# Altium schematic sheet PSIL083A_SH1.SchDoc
size 431 x 279 mm; Date: Not shown in title block; ApprovedBy: Not shown in title block; CheckedBy: Not shown in title block; Author: Not shown in title block; CompanyName: Not shown in title block; Engineer: Not shown in title block; Organization: Not shown in title block; Address1: Not shown in title block; Address2: Not shown in title block; Address3: Not shown in title block; Address4: Not shown in title block; DocumentNumber: 1; Revision: Use project parameter SCH_Rev; SheetNumber: 1; SheetTotal: 3; PageSetup: Record=PageOptions¦CenterHorizontal=True¦CenterVertical=True¦PrintScale=1.00¦XCorrection=1.00¦YCorrection=1.00¦PrintKind=0¦BorderSize=5000000¦LeftOffset=0¦BottomOffset=0¦Orientation=2¦PaperLength=1000¦PaperWidth=1000¦Scale=100¦PaperSource=15¦PrintQuality=600¦MediaType=1¦DitherType=10¦PaperKind=Letter¦PrintScaleMode=1
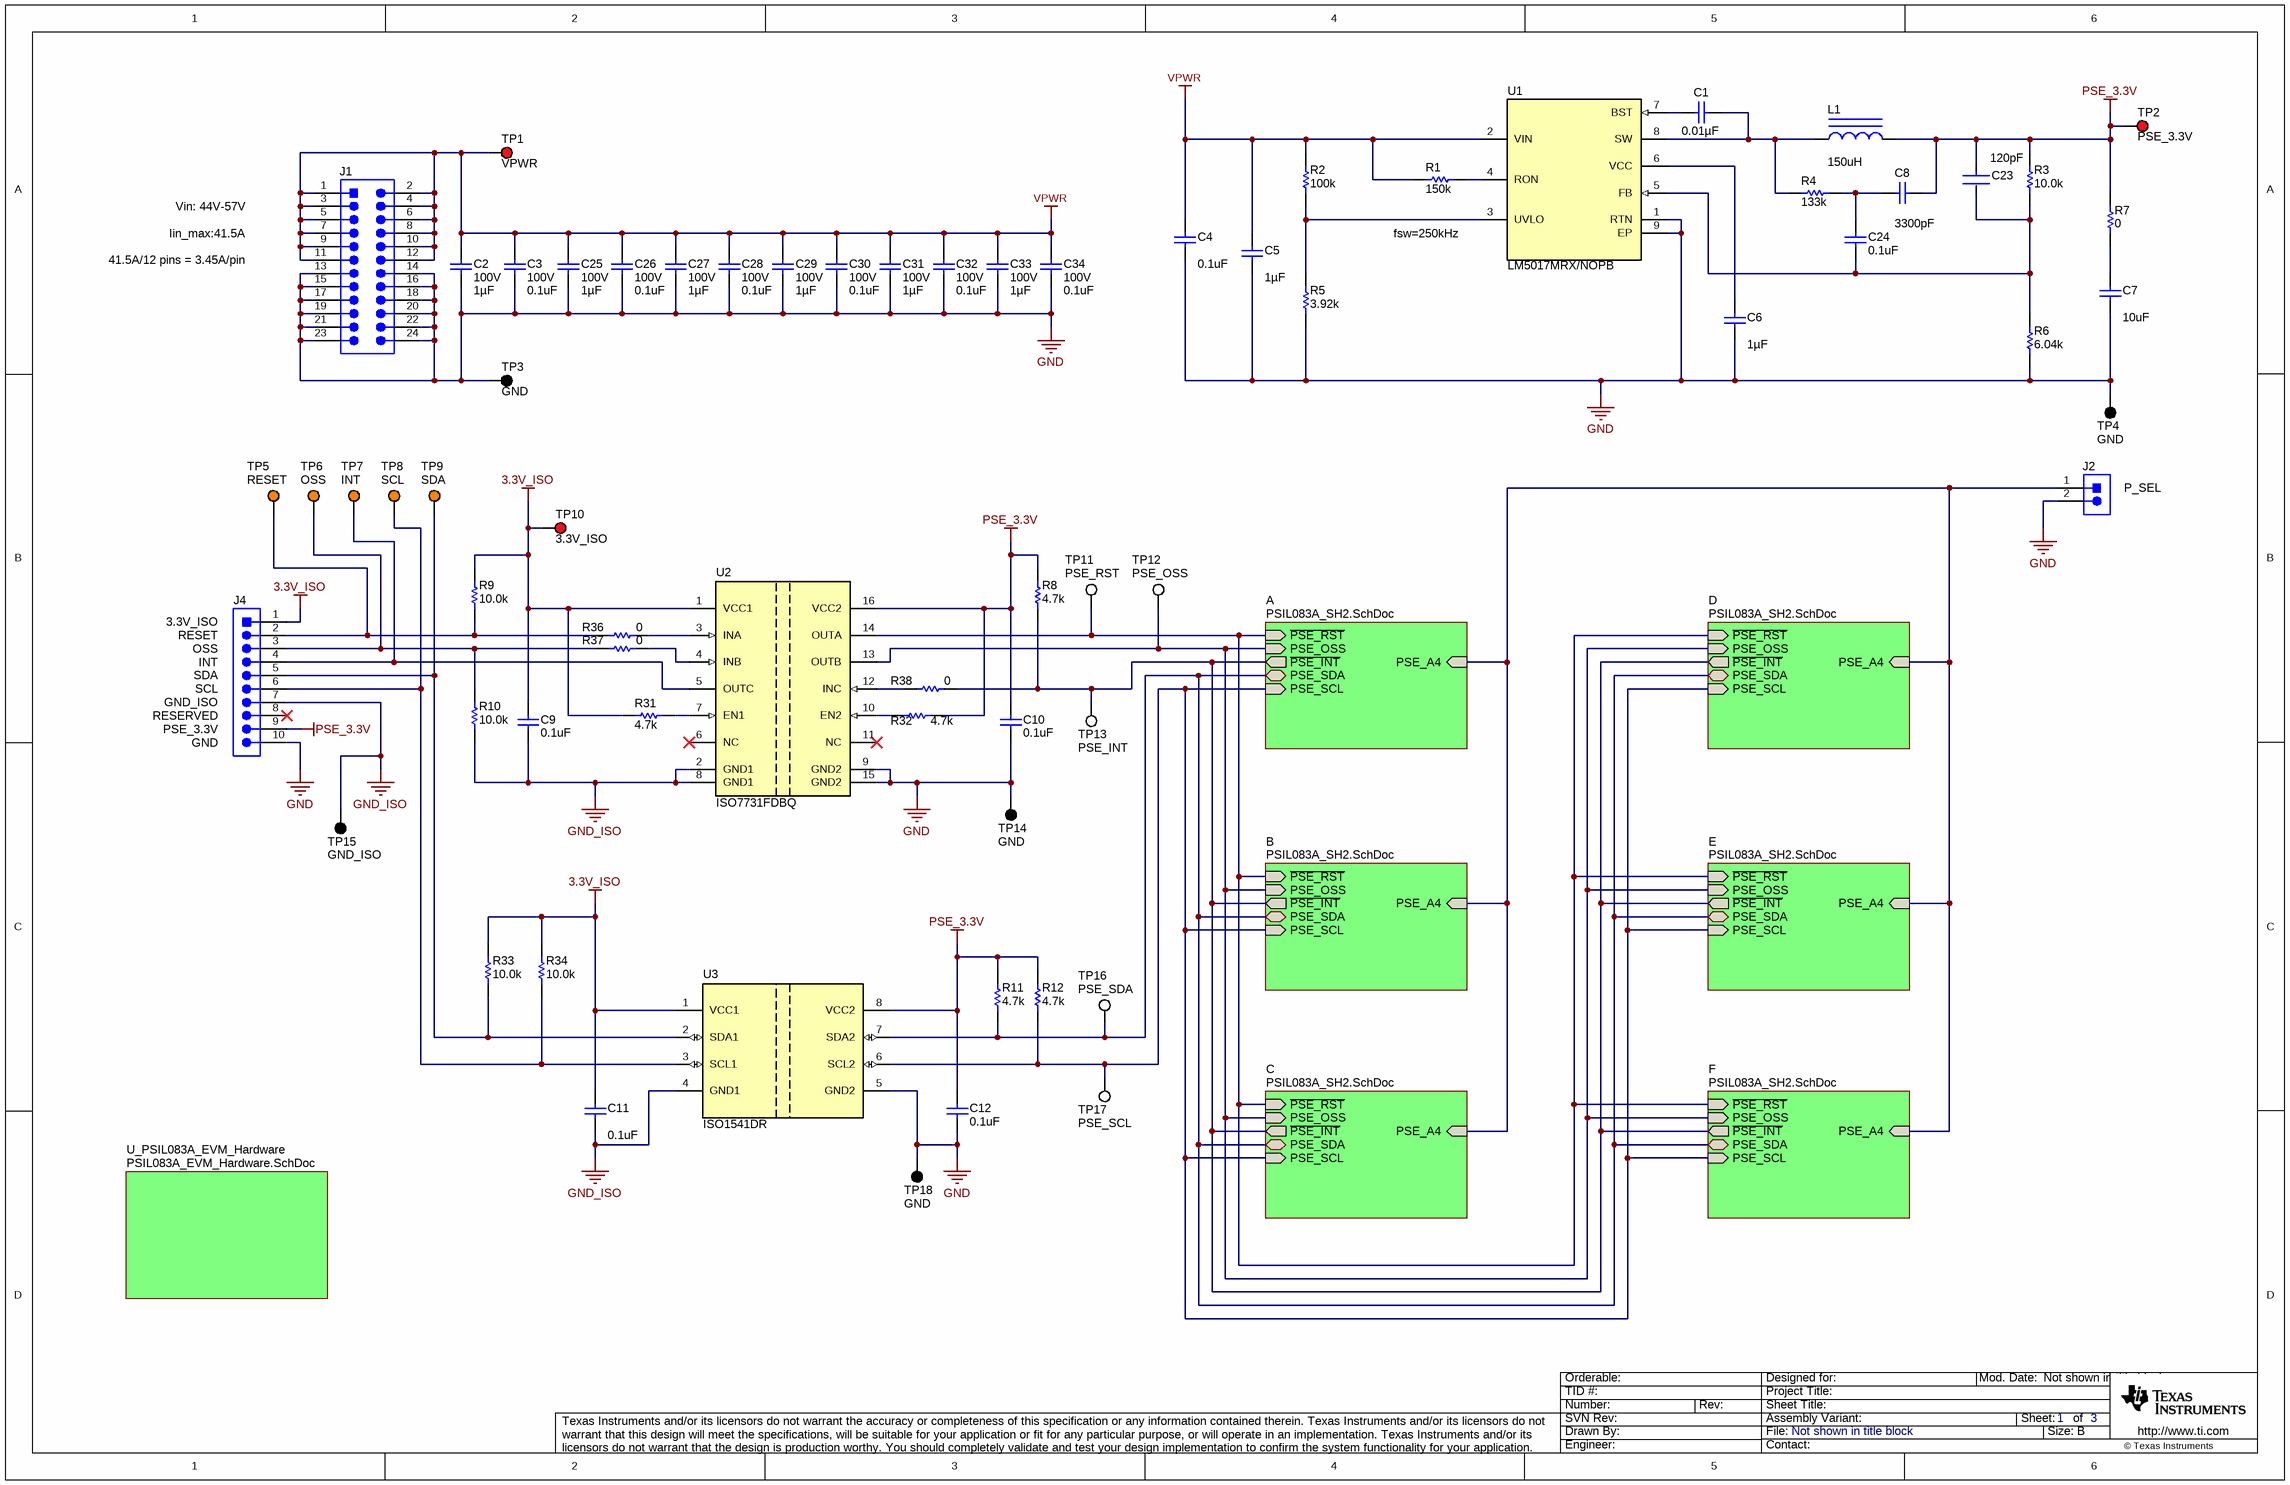
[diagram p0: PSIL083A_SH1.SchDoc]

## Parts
C1  ValueDisplayed: 0.01µF  [0603]  (hidden comment: 885012206089)
C2  VDC_V: 100V  ValueDisplayed: 1µF  [1206]  (hidden comment: GCJ31CR72A105KA01K)
C3  VDC_V: 100V  ValueDisplayed: 0.1uF  [0805_HV]  (hidden comment: C2012X7R2A104K125AA)
C4  ValueDisplayed: 0.1uF  [0805_HV]  (hidden comment: C2012X7R2A104K125AA)
C5  ValueDisplayed: 1µF  [1206]  (hidden comment: GCJ31CR72A105KA01K)
C6  ValueDisplayed: 1µF  [0603]  (hidden comment: CL10B105MO8NNWC)
C7  ValueDisplayed: 10uF  [0805_HV]  (hidden comment: 885012207026)
C8  ValueDisplayed: 3300pF  [0603]  (hidden comment: GRM1885C1H332JA01D)
C9  ValueDisplayed: 0.1uF  [0603]  (hidden comment: 885012206095)
C10  ValueDisplayed: 0.1uF  [0603]  (hidden comment: 885012206095)
C11  ValueDisplayed: 0.1uF  [0603]  (hidden comment: 885012206095)
C12  ValueDisplayed: 0.1uF  [0603]  (hidden comment: 885012206095)
C23  Cap_F: 120pF  [FP-GCM1555C1H121FA16D_0402-MFG]  (hidden comment: GCM1555C1H121FA16D)
C24  ValueDisplayed: 0.1uF  [0603]  (hidden comment: 885012206095)
C25  VDC_V: 100V  ValueDisplayed: 1µF  [1206]  (hidden comment: GCJ31CR72A105KA01K)
C26  VDC_V: 100V  ValueDisplayed: 0.1uF  [0805_HV]  (hidden comment: C2012X7R2A104K125AA)
C27  VDC_V: 100V  ValueDisplayed: 1µF  [1206]  (hidden comment: GCJ31CR72A105KA01K)
C28  VDC_V: 100V  ValueDisplayed: 0.1uF  [0805_HV]  (hidden comment: C2012X7R2A104K125AA)
C29  VDC_V: 100V  ValueDisplayed: 1µF  [1206]  (hidden comment: GCJ31CR72A105KA01K)
C30  VDC_V: 100V  ValueDisplayed: 0.1uF  [0805_HV]  (hidden comment: C2012X7R2A104K125AA)
C31  VDC_V: 100V  ValueDisplayed: 1µF  [1206]  (hidden comment: GCJ31CR72A105KA01K)
C32  VDC_V: 100V  ValueDisplayed: 0.1uF  [0805_HV]  (hidden comment: C2012X7R2A104K125AA)
C33  VDC_V: 100V  ValueDisplayed: 1µF  [1206]  (hidden comment: GCJ31CR72A105KA01K)
C34  VDC_V: 100V  ValueDisplayed: 0.1uF  [0805_HV]  (hidden comment: C2012X7R2A104K125AA)
J1  TSW-112-07-G-D  [TSW-112-07-G-D]  (value not drawn)
J2  TSW-102-07-G-S  [TSW-102-07-G-S]  (value not drawn)
J4  TSW-110-07-G-S  [TSW-110-07-G-S]  (value not drawn)
L1  ValueDisplayed: 150uH  [WE-TPC_6823]  (hidden comment: 744062151)
R1  ValueDisplayed: 150k  [0402]  (hidden comment: CRCW0402150KFKED)
R2  ValueDisplayed: 100k  [0402]  (hidden comment: CRCW0402100KFKED)
R3  ValueDisplayed: 10.0k  [0402]  (hidden comment: CRCW040210K0FKED)
R4  ValueDisplayed: 133k  [0402]  (hidden comment: CRCW0402133KFKED)
R5  ValueDisplayed: 3.92k  [0402]  (hidden comment: CRCW04023K92FKED)
R6  ValueDisplayed: 6.04k  [0402]  (hidden comment: CRCW04026K04FKED)
R7  ValueDisplayed: 0  [0603]  (hidden comment: RC0603JR-070RL)
R8  ValueDisplayed: 4.7k  [0402]  (hidden comment: CRCW04024K70JNED)
R9  ValueDisplayed: 10.0k  [0402]  (hidden comment: CRCW040210K0FKED)
R10  ValueDisplayed: 10.0k  [0402]  (hidden comment: CRCW040210K0FKED)
R11  ValueDisplayed: 4.7k  [0402]  (hidden comment: CRCW04024K70JNED)
R12  ValueDisplayed: 4.7k  [0402]  (hidden comment: CRCW04024K70JNED)
R31  ValueDisplayed: 4.7k  [0402]  (hidden comment: CRCW04024K70JNED)
R32  ValueDisplayed: 4.7k  [0402]  (hidden comment: CRCW04024K70JNED)
R33  ValueDisplayed: 10.0k  [0402]  (hidden comment: CRCW040210K0FKED)
R34  ValueDisplayed: 10.0k  [0402]  (hidden comment: CRCW040210K0FKED)
R36  ValueDisplayed: 0  [0402]  (hidden comment: ERJ-2GE0R00X)
R37  ValueDisplayed: 0  [0402]  (hidden comment: ERJ-2GE0R00X)
R38  ValueDisplayed: 0  [0402]  (hidden comment: ERJ-2GE0R00X)
TP1  VPWR  [Keystone5000]
TP2  PSE_3.3V  [Keystone5000]
TP3  GND  [Keystone5001]
TP4  GND  [Keystone5001]
TP5  RESET  [Keystone5003]
TP6  OSS  [Keystone5003]
TP7  INT  [Keystone5003]
TP8  SCL  [Keystone5003]
TP9  SDA  [Keystone5003]
TP10  3.3V_ISO  [Keystone5000]
TP11  PSE_RST  [Keystone5002]
TP12  PSE_OSS  [Keystone5002]
TP13  PSE_INT  [Keystone5002]
TP14  GND  [Keystone5001]
TP15  GND_ISO  [Keystone5001]
TP16  PSE_SDA  [Keystone5002]
TP17  PSE_SCL  [Keystone5002]
TP18  GND  [Keystone5001]
U1  LM5017MRX/NOPB  [DDA0008B_N]
U2  ISO7731FDBQ  [DBQ0016A_N]
U3  ISO1541DR  [D0008B_L]

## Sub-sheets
A = PSIL083A_SH2.SchDoc: ~{PSE_RST} (in), PSE_SCL (in), PSE_OSS (in), ~{PSE_INT} (out), PSE_A4 (in), PSE_SDA (bidir)
B = PSIL083A_SH2.SchDoc: ~{PSE_RST} (in), PSE_SCL (in), PSE_OSS (in), ~{PSE_INT} (out), PSE_A4 (in), PSE_SDA (bidir)
C = PSIL083A_SH2.SchDoc: ~{PSE_RST} (in), PSE_SCL (in), PSE_OSS (in), ~{PSE_INT} (out), PSE_A4 (in), PSE_SDA (bidir)
D = PSIL083A_SH2.SchDoc: ~{PSE_RST} (in), PSE_SCL (in), PSE_OSS (in), ~{PSE_INT} (out), PSE_A4 (in), PSE_SDA (bidir)
E = PSIL083A_SH2.SchDoc: ~{PSE_RST} (in), PSE_SCL (in), PSE_OSS (in), ~{PSE_INT} (out), PSE_A4 (in), PSE_SDA (bidir)
F = PSIL083A_SH2.SchDoc: ~{PSE_RST} (in), PSE_SCL (in), PSE_OSS (in), ~{PSE_INT} (out), PSE_A4 (in), PSE_SDA (bidir)
U_PSIL083A_EVM_Hardware = PSIL083A_EVM_Hardware.SchDoc: no entries

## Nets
3.3V_ISO: C9.1 C11.1 J4.1 R9.1 R31.2 R33.1 R34.1 TP10.1 U2.1(VCC1) U3.1(VCC1)
GND: C2.1 C3.1 C4.1 C5.1 C6.2 C7.2 C10.2 C12.2 C25.1 C26.1 C27.1 C28.1 C29.1 C30.1 C31.1 C32.1 C33.1 C34.1 J1.13 J1.14 J1.15 J1.16 J1.17 J1.18 J1.19 J1.20 J1.21 J1.22 J1.23 J1.24 J2.2 J4.10 R5.2 R6.2 TP3.1 TP4.1 TP14.1 TP18.1 U1.1(RTN) U1.9(EP) U2.9(GND2) U2.15(GND2) U3.5(GND2)
GND_ISO: C9.2 C11.2 J4.7 R10.2 TP15.1 U2.2(GND1) U2.8(GND1) U3.4(GND1)
PSE_3.3V: C8.1 C10.1 C12.1 C23.1 J4.9 L1.2 R3.1 R7.1 R8.2 R11.2 R12.2 R32.1 TP2.1 U2.16(VCC2) U3.8(VCC2)
VPWR: C2.2 C3.2 C4.2 C5.2 C25.2 C26.2 C27.2 C28.2 C29.2 C30.2 C31.2 C32.2 C33.2 C34.2 J1.1 J1.2 J1.3 J1.4 J1.5 J1.6 J1.7 J1.8 J1.9 J1.10 J1.11 J1.12 R1.1 R2.1 TP1.1 U1.2(VIN)
NetC1_1: C1.1 L1.1 R4.1 U1.8(SW)
NetC1_2: C1.2 U1.7(BST)
NetC6_1: C6.1 U1.6(VCC)
NetC7_1: C7.1 R7.2
NetC8_2: C8.2 C24.1 R4.2
NetC23_2: C23.2 C24.2 R3.2 R6.1 U1.5(FB)
NetJ2_1: J2.1 ; sheet A/PSE_A4, sheet B/PSE_A4, sheet C/PSE_A4, sheet D/PSE_A4, sheet E/PSE_A4, sheet F/PSE_A4
NetJ4_2: J4.2 R9.2 R36.1 TP5.1
NetJ4_3: J4.3 R10.1 R37.1 TP6.1
NetJ4_4: J4.4 TP7.1 U2.5(OUTC)
NetJ4_5: J4.5 R33.2 TP9.1 U3.2(SDA1)
NetJ4_6: J4.6 R34.2 TP8.1 U3.3(SCL1)
NetR1_2: R1.2 U1.4(RON)
NetR2_2: R2.2 R5.1 U1.3(UVLO)
NetR8_1: R8.1 R38.2 TP13.1 ; sheet A/~{PSE_INT}, sheet B/~{PSE_INT}, sheet C/~{PSE_INT}, sheet D/~{PSE_INT}, sheet E/~{PSE_INT}, sheet F/~{PSE_INT}
NetR11_1: R11.1 TP16.1 U3.7(SDA2) ; sheet A/PSE_SDA, sheet B/PSE_SDA, sheet C/PSE_SDA, sheet D/PSE_SDA, sheet E/PSE_SDA, sheet F/PSE_SDA
NetR12_1: R12.1 TP17.1 U3.6(SCL2) ; sheet A/PSE_SCL, sheet B/PSE_SCL, sheet C/PSE_SCL, sheet D/PSE_SCL, sheet E/PSE_SCL, sheet F/PSE_SCL
NetR31_1: R31.1 U2.7(EN1)
NetR32_2: R32.2 U2.10(EN2)
NetR36_2: R36.2 U2.3(INA)
NetR37_2: R37.2 U2.4(INB)
NetR38_1: R38.1 U2.12(INC)
NetTP11_1: TP11.1 U2.14(OUTA) ; sheet A/~{PSE_RST}, sheet B/~{PSE_RST}, sheet C/~{PSE_RST}, sheet D/~{PSE_RST}, sheet E/~{PSE_RST}, sheet F/~{PSE_RST}
NetTP12_1: TP12.1 U2.13(OUTB) ; sheet A/PSE_OSS, sheet B/PSE_OSS, sheet C/PSE_OSS, sheet D/PSE_OSS, sheet E/PSE_OSS, sheet F/PSE_OSS

Not connected (* = marked no-connect by the designer): J4 8*; U2 6(NC)* 11(NC)*

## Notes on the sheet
- Vin: 44V-57V
- Iin_max:41.5A
- fsw=250kHz
- 41.5A/12 pins = 3.45A/pin
- (near J2) P_SEL
- (near J4) 3.3V_ISO
- (near J4) RESET
- (near J4) OSS
- (near J4) INT
- (near J4) SDA
- (near J4) SCL
- (near J4) GND_ISO
- (near J4) GND
- (near J4) PSE_3.3V
- (near J4) RESERVED

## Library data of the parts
C1 = CMP-0750039-1: CAP, CERM, 0.01 µF, 50 V,+/- 10%, X7R, 0603; Manufacturer: Wurth Elektronik; Polarized: N; AEC Category: Q200; TaMax_C: 125°C; SizeAreaWB_mm2: 4.68; Value: 0.01uF; CompType: Capacitor; SizeArea_mm2: 1.28; SizeY_mm: 0.8; SizeZ_mm: 1; SizeX_mm: 1.6; VDC_V: 50V; U/M: EA; Cap_F: 10nF; TaMin_C: -55°C
C2 C25 C27 C29 C31 C33 = CMP-0750040-1: CAP, CERM, 1 µF, 100 V,+/- 10%, X7R, AEC-Q200 Grade 1, 1206; Manufacturer: MuRata; Value: 1uF; U/M: EA; SizeX_mm: 3.2; Polarized: N; TaMin_C: -55°C; SizeZ_mm: 1.35; SizeY_mm: 1.6; AEC Category: Q200; SizeArea_mm2: 5.12; TaMax_C: 125°C; AEC Grade: 1; CompType: Capacitor; AEC Qualified: Y; SizeAreaWB_mm2: 10.92
C3 C26 C28 C30 C32 C34 = CMP-0007886-2: CAP, CERM, 0.1 uF, 100 V, +/- 10%, X7R, 0805; Manufacturer: TDK; TaMin_C: -55°C; ESR_ohm: 0.020726; Polarized: N; SizeAreaWB_mm2: 6.75; Value1: 0.020726 ohm; U/M: EA; Value: 0.1uF; TaMax_C: 125°C; SizeZ_mm: 1.45; SizeX_mm: 2; SizeY_mm: 1.25; Cap_Case: 0805; SizeArea_mm2: 2.5; Cap_F: 100nF; IRMS_A: 1.456A; AEC Category: Q200
C4 = CMP-0007886-2: CAP, CERM, 0.1 uF, 100 V, +/- 10%, X7R, 0805; Manufacturer: TDK; TaMin_C: -55°C; ESR_ohm: 0.020726; Polarized: N; SizeAreaWB_mm2: 6.75; Value1: 0.020726 ohm; U/M: EA; Value: 0.1uF; TaMax_C: 125°C; SizeZ_mm: 1.45; SizeX_mm: 2; SizeY_mm: 1.25; Cap_Case: 0805; Value2: 100V; SizeArea_mm2: 2.5; CompType: Capacitor; Cap_F: 100nF; IRMS_A: 1.456A; AEC Category: Q200
C5 = CMP-0750040-1: CAP, CERM, 1 µF, 100 V,+/- 10%, X7R, AEC-Q200 Grade 1, 1206; Manufacturer: MuRata; Value: 1uF; VDC_V: 100V; U/M: EA; SizeX_mm: 3.2; Polarized: N; TaMin_C: -55°C; SizeZ_mm: 1.35; SizeY_mm: 1.6; AEC Category: Q200; SizeArea_mm2: 5.12; TaMax_C: 125°C; AEC Grade: 1; CompType: Capacitor; AEC Qualified: Y; SizeAreaWB_mm2: 10.92
C6 = CMP-0082012-1: CAP, CERM, 1 µF, 16 V,+/- 20%, X7R, 0603; Manufacturer: Samsung; SizeAreaWB_mm2: 4.68; SizeArea_mm2: 1.28; AEC Qualified: N; AEC Category: Q200; Value: 1uF; TaMax_C: 125°C; SizeZ_mm: 1; TaMin_C: -55°C; VDC_V: 16V; SizeY_mm: 0.8; U/M: EA; CompType: Capacitor; SizeX_mm: 1.6
C7 = CMP-0007691-2: CAP, CERM, 10 uF, 10 V, +/- 10%, X7R, 0805; Manufacturer: Wurth Elektronik; TaMin_C: -55°C; Polarized: N; SizeAreaWB_mm2: 6.75; Value1: Unknown; U/M: EA; Value: 10uF; TaMax_C: 125°C; SizeZ_mm: 1.45; SizeX_mm: 2; SizeY_mm: 1.25; Cap_Case: 0805; Value2: 10V; SizeArea_mm2: 2.5; CompType: Capacitor; Cap_F: 10µF; AEC Category: Q200
C8 = CMP-0007210-4: CAP, CERM, 3300 pF, 50 V, +/- 5%, C0G/NP0, 0603; Manufacturer: MuRata; TaMin_C: -55°C; Polarized: N; SizeAreaWB_mm2: 4.68; Value1: Unknown; U/M: EA; Value: 3300pF; TaMax_C: 125°C; SizeZ_mm: 1; SizeX_mm: 1.6; SizeY_mm: 0.8; Value2: 50V; SizeArea_mm2: 1.28; CompType: Capacitor; Cap_F: 3.3nF; AEC Category: Q200
C9-C12 C24 = CMP-0006837-4: CAP, CERM, 0.1 uF, 50 V, +/- 10%, X7R, 0603; Manufacturer: Wurth Elektronik; TaMin_C: -55°C; Polarized: N; SizeAreaWB_mm2: 4.68; Value1: Unknown; U/M: EA; Value: 0.1uF; TaMax_C: 125°C; SizeZ_mm: 1; SizeX_mm: 1.6; SizeY_mm: 0.8; Value2: 50V; SizeArea_mm2: 1.28; CompType: Capacitor; Cap_F: 100nF; AEC Category: Q200
C23 = CMP-0086511-1: 120pF ±1% 50V Ceramic Capacitor C0G, NP0 0402 (1005 Metric); Manufacturer: Murata; AEC Qualified: Yes; TempCo: 30ppm/°C; SizeZ_mm: 0.55mm; Symbol Name: SYM-GCM1555C1H121FA16D; AEC Grade: Grade 1
J1 = CMP-0075423-1: Header, 100mil, 12x2, Gold, TH; Manufacturer: Samtec; Pitch_mm: 2.54; Cert_VDE: N; Gender: Male; Cert_CSA: Y; Current_A: 6.3A; Voltage_V: 550V; CT: False; Row_Count: 2; CNHeader: True
J2 = CMP-0075405-2: Header, 100mil, 2x1, Gold, TH; Manufacturer: Samtec; Pitch_mm: 2.54; Cert_VDE: N; Gender: Male; Cert_CSA: Y; Voltage_V: 550V; Green_REACh: Passed; Current_A: 6.3A; Green_Lifecycle: Active; Row_Count: 1
J4 = CMP-0075422-1: Header, 100mil, 10x1, Gold, TH; Manufacturer: Samtec; Pitch_mm: 2.54; Cert_VDE: N; Gender: Male; Cert_CSA: Y; Voltage_V: 550V; Green_REACh: Passed; Current_A: 6.3A; CT: False; Green_Lifecycle: Active; Row_Count: 1; CNHeader: True
L1 = CMP-0064704-3: Inductor, Shielded Drum Core, Ferrite, 150 uH, 0.36 A, 0.605 ohm, SMD; Manufacturer: Wurth Elektronik; Isat: 0.36A @ 35% inductance drop; Irms: 0.43A @ 30C rise; Green_Lifecycle: Active; SizeAreaWB_mm2: 77.44; DCR_ohm: 6.05d; Green_REACh: Passed; Value: 150uH; Imax_A: 3.6dA; SizeZ_mm: 2.5; SizeX_mm: 6.8; Value2: 0.36A; SizeArea_mm2: 46.24; Ind_H: 150µH; AEC Qualified: N; AEC Category: Q200
R1 = CMP-0026021-3: RES, 150 k, 1%, 0.063 W, AEC-Q200 Grade 0, 0402; Manufacturer: Vishay-Dale; Power_W: 63mW; TempCo: 100 ppm/C; Value: 150k; EIA_Code: E96; SizeX_mm: 1; SizeY_mm: 0.5; SizeZ_mm: 0.6; Value2: 0.063W; AEC Qualified: Y; VDC_V: 50V; AEC Category: Q200; AEC Grade: 0
R2 = CMP-0025950-3: RES, 100 k, 1%, 0.063 W, AEC-Q200 Grade 0, 0402; Manufacturer: Vishay-Dale; Power_W: 63mW; TempCo: 100 ppm/C; Value: 100k; EIA_Code: E96; SizeX_mm: 1; SizeY_mm: 0.5; SizeZ_mm: 0.6; Value2: 0.063W; AEC Qualified: Y; VDC_V: 50V; AEC Category: Q200; AEC Grade: 0
R3 R9 R10 R33 R34 = CMP-0025958-3: RES, 10.0 k, 1%, 0.063 W, AEC-Q200 Grade 0, 0402; Manufacturer: Vishay-Dale; Power_W: 63mW; TempCo: 100 ppm/C; Value_Code: 10k0; Value: 10.0k; EIA_Code: E96; Res_ohm: 10k; SizeX_mm: 1; SizeY_mm: 0.5; SizeZ_mm: 0.6; Value2: 0.063W; AEC Qualified: Y; VDC_V: 50V; AEC Category: Q200; AEC Grade: 0
R4 = CMP-0025999-3: RES, 133 k, 1%, 0.063 W, AEC-Q200 Grade 0, 0402; Manufacturer: Vishay-Dale; Power_W: 63mW; TempCo: 100 ppm/C; Value: 133k; EIA_Code: E96; SizeX_mm: 1; SizeY_mm: 0.5; SizeZ_mm: 0.6; Value2: 0.063W; AEC Qualified: Y; VDC_V: 50V; AEC Category: Q200; AEC Grade: 0
R5 = CMP-0026340-2: RES, 3.92 k, 1%, 0.063 W, AEC-Q200 Grade 0, 0402; Manufacturer: Vishay-Dale; Power_W: 63mW; TempCo: 100 ppm/C; Value_Code: 3k92; Value: 3.92k; EIA_Code: E96; SizeX_mm: 1; SizeY_mm: 0.5; SizeZ_mm: 0.6; Value2: 0.063W; AEC Qualified: Y; VDC_V: 50V; AEC Category: Q200; AEC Grade: 0
R6 = CMP-0026512-2: RES, 6.04 k, 1%, 0.063 W, AEC-Q200 Grade 0, 0402; Manufacturer: Vishay-Dale; Power_W: 63mW; TempCo: 100 ppm/C; Value_Code: 6k04; Value: 6.04k; EIA_Code: E96; SizeX_mm: 1; SizeY_mm: 0.5; SizeZ_mm: 0.6; Value2: 0.063W; AEC Qualified: Y; VDC_V: 50V; AEC Category: Q200; AEC Grade: 0
R7 = CMP-0025885-5: RES, 0, 5%, 0.1 W, 0603; Manufacturer: Yageo; Power_W: 100mW; TempCo: 200 ppm/C; Value_Code: 0000; Value: 0; EIA_Code: E24; SizeX_mm: 1.6; SizeZ_mm: 1; Value2: 0.1W; SizeArea_mm2: 1.28; AEC Qualified: N; VDC_V: 75V; AEC Category: Q200; SizeY_mm: 0.8; SizeAreaWB_mm2: 4.68
R8 R11 R12 R31 R32 = CMP-0026938-5: RES, 4.7 k, 5%, 0.063 W, AEC-Q200 Grade 0, 0402; Manufacturer: Vishay-Dale; Power_W: 63mW; TempCo: 200 ppm/C; Value_Code: 4k70; Value: 4.7k; EIA_Code: E24; SizeX_mm: 1; SizeY_mm: 0.5; SizeZ_mm: 0.6; Value2: 0.063W; AEC Qualified: Y; VDC_V: 50V; AEC Grade: 0; AEC Category: Q200
R36-R38 = CMP-0026992-3: RES, 0, 5%, 0.1 W, AEC-Q200 Grade 0, 0402; Manufacturer: Panasonic; Power_W: 100mW; TempCo: 600 ppm/C; Value_Code: 0000; Value: 0; EIA_Code: E24; SizeX_mm: 1; SizeY_mm: 0.5; SizeZ_mm: 0.6; Value2: 0.1W; AEC Qualified: Y; VDC_V: 50V; AEC Category: Q200; SizeAreaWB_mm2: 3
TP1 TP2 TP10 = CMP-0055137-1: Test Point, Miniature, Red, TH; Manufacturer: Keystone; PartNumber: 5000; CNHeader: FALSE; Green_Lifecycle: Active; Green_REACh: Passed; ContactFinish: Silver; CT: TRUE
TP3 TP4 TP14 TP15 TP18 = CMP-0055138-1: Test Point, Miniature, Black, TH; Manufacturer: Keystone; PartNumber: 5001; CNHeader: FALSE; Green_Lifecycle: Active; Green_REACh: Passed; ContactFinish: Silver; CT: TRUE
TP5-TP9 = CMP-0055140-1: Test Point, Miniature, Orange, TH; Manufacturer: Keystone; PartNumber: 5003; CNHeader: FALSE; Green_Lifecycle: Active; Green_REACh: Passed; ContactFinish: Silver; CT: TRUE
TP11-TP13 TP16 TP17 = CMP-0055139-1: Test Point, Miniature, White, TH; Manufacturer: Keystone; PartNumber: 5002; CNHeader: FALSE; Green_Lifecycle: Active; Green_REACh: Passed; ContactFinish: Silver; CT: TRUE
U1 = CMP-0066086-2: 7.5-100V Wide Vin, 600mA Constant On-Time Synchronous Buck Regulator, DDA0008B (SOIC-8); Manufacturer: Texas Instruments; Alternate PartNumber: LM5017MR/NOPB; SizeX_mm: 5.0; SizeY_mm: 6.2; CompType: IC; SizeZ_mm: 1.7; SizeArea_mm2: 31.0; SizeAreaWB_mm2: 57.4; U/M: EA
U2 = CMP-0078720-1: High Speed, Robust EMC Triple-Channel Digital Isolators, DBQ0016A (SSOP-16); Alternate PartNumber: ISO7731FDBQR; Manufacturer: Texas Instruments; SizeZ_mm: 1.75; SizeX_mm: 6; SizeY_mm: 10; SizeArea_mm2: 60; CompType: IC; SizeAreaWB_mm2: 96; AEC Qualified: N; AEC Category: Q200
U3 = CMP-0076085-2: 2.5 kVrms Isolated Unidirectional Clock, Bidirectional I2C Isolators, D0008B (SOIC-8); Manufacturer: Texas Instruments; SizeAreaWB_mm2: 55.2; SizeArea_mm2: 29.4; SizeZ_mm: 1.75; SizeY_mm: 4.9; CompType: IC; SizeX_mm: 6.0; AEC Qualified: N; Rating: Catalog; AEC Category: Q200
